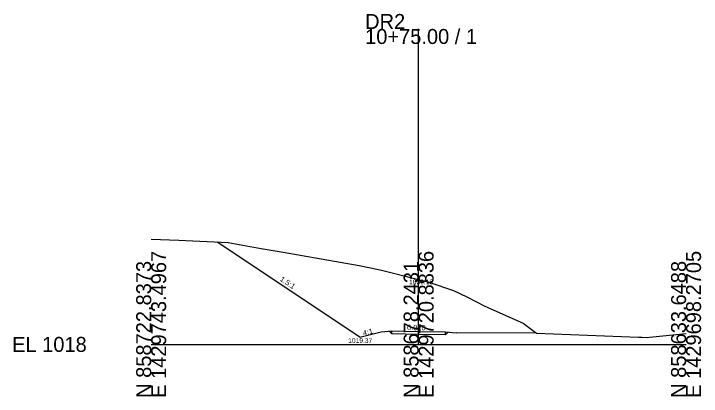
# Model space of a CAD drawing. Extents: x -26 to 103, y -10 to 3026.
# Drawn here: x -25.7 to 102.8, y 1490.3 to 1561.8 of the extents above; entities that cross this region are included whole.
import ezdxf

# ---------------------------------------------------------------- set-up
doc = ezdxf.new("R2010")
doc.units = 0
for name, color, linetype in [('Default', 7, 'Continuous'), ('Exist Cross Section Cell', 7, 'Continuous'), ('Exist XS Center Line Elevation Label', 7, 'Continuous'), ('Exist XS Ground Line', 7, 'Continuous'), ('Prop CMT Pvmt Surface', 7, 'Continuous'), ('Prop CMT Shld Paved Course 1', 7, 'Continuous'), ('Prop CMT Slope Grass', 7, 'Continuous'), ('Prop CMT Subgrade Earthwork', 7, 'Continuous'), ('Prop CMT Template Flag', 7, 'Continuous'), ('Prop XS SE Text', 7, 'Continuous'), ('Prop XS Side Slope Text', 7, 'Continuous')]:
    doc.layers.add(name, color=color, linetype=linetype)

msp = doc.modelspace()

# ---------------------------------------------------------------- linework, layer by layer
at = {"layer": 'Exist Cross Section Cell'}
for p, q in [((50, 1500), (50, 1558.96)), ((0, 1500), (50, 1500)), ((50, 1500), (100, 1500))]:
    msp.add_line(p, q, dxfattribs=at)
at = {"layer": 'Exist XS Ground Line'}
msp.add_lwpolyline([(0, 1519.65), (5.17, 1519.47), (14.37, 1519.03), (20.54, 1517.9), (24.69, 1517.27), (38.86, 1514.75), (42.78, 1513.94), (50, 1512.13), (51.93, 1511.65), (56.52, 1510.06), (58.99, 1508.89), (62.38, 1507.12), (69.52, 1503.94), (72.06, 1502.11), (91.08, 1501.36), (91.72, 1501.32), (92.7, 1501.27), (93.19, 1501.33), (100, 1502.02)], dxfattribs=at)
at = {"layer": 'Prop CMT Pvmt Surface'}
for p, q in [((45, 1502.53), (50, 1502.43)), ((50, 1502.43), (55, 1502.33))]:
    msp.add_line(p, q, dxfattribs=at)
at = {"layer": 'Prop CMT Shld Paved Course 1'}
for points in [[(45, 1501.98), (45, 1502.53)], [(55, 1501.78), (55, 1502.33)]]:
    msp.add_lwpolyline(points, dxfattribs=at)
at = {"layer": 'Prop CMT Slope Grass'}
for p, q in [((39, 1501.37), (12.36, 1519.13)), ((39, 1501.37), (43, 1502.37)), ((43, 1502.37), (45, 1502.53)), ((55, 1502.33), (57, 1502.17)), ((72.06, 1502.11), (57, 1502.17))]:
    msp.add_line(p, q, dxfattribs=at)
at = {"layer": 'Prop CMT Subgrade Earthwork'}
for points in [[(45, 1501.98), (44.5, 1502.49)], [(55, 1501.78), (55.5, 1502.29)]]:
    msp.add_lwpolyline(points, dxfattribs=at)
at = {"layer": 'Prop CMT Template Flag'}
for p, q in [((50, 1501.88), (45, 1501.98)), ((55, 1501.78), (50, 1501.88))]:
    msp.add_line(p, q, dxfattribs=at)

# ---------------------------------------------------------------- texts
at = {"layer": 'Default'}
msp.add_text('1019.37', height=0.9, dxfattribs=at).set_placement((36.83, 1500.26))
at = {"layer": 'Exist Cross Section Cell'}
for s, p in [('DR2', (40, 1558.96)), ('10+75.00 / 1', (40, 1556.16)), ('EL 1018', (-26, 1498.6))]:
    msp.add_text(s, height=2.8, dxfattribs=at).set_placement(p)
for s, p in [('E 1429743.4967', (2.8, 1490)), ('E 1429720.8836', (52.8, 1490)), ('E 1429698.2705', (102.8, 1490)), ('N 858722.8373', (0, 1490)), ('N 858678.2431', (50, 1490)), ('N 858633.6488', (100, 1490))]:
    msp.add_text(s, height=2.8, rotation=90, dxfattribs=at).set_placement(p)
at = {"layer": 'Exist XS Center Line Elevation Label'}
msp.add_text('1030.13', height=0.9, dxfattribs=at).set_placement((48.22, 1511.23))
at = {"layer": 'Prop XS SE Text'}
msp.add_text('0.020', height=1, rotation=358.8542, dxfattribs=at).set_placement((47.84, 1502.68))
at = {"layer": 'Prop XS Side Slope Text'}
for s, rotation, p in [('1.5:1', 326.3099, (23.97, 1511.97)), ('4:1', 14.0362, (39.69, 1501.61))]:
    msp.add_text(s, height=1, rotation=rotation, dxfattribs=at).set_placement(p)

doc.saveas('drawing.dxf')
